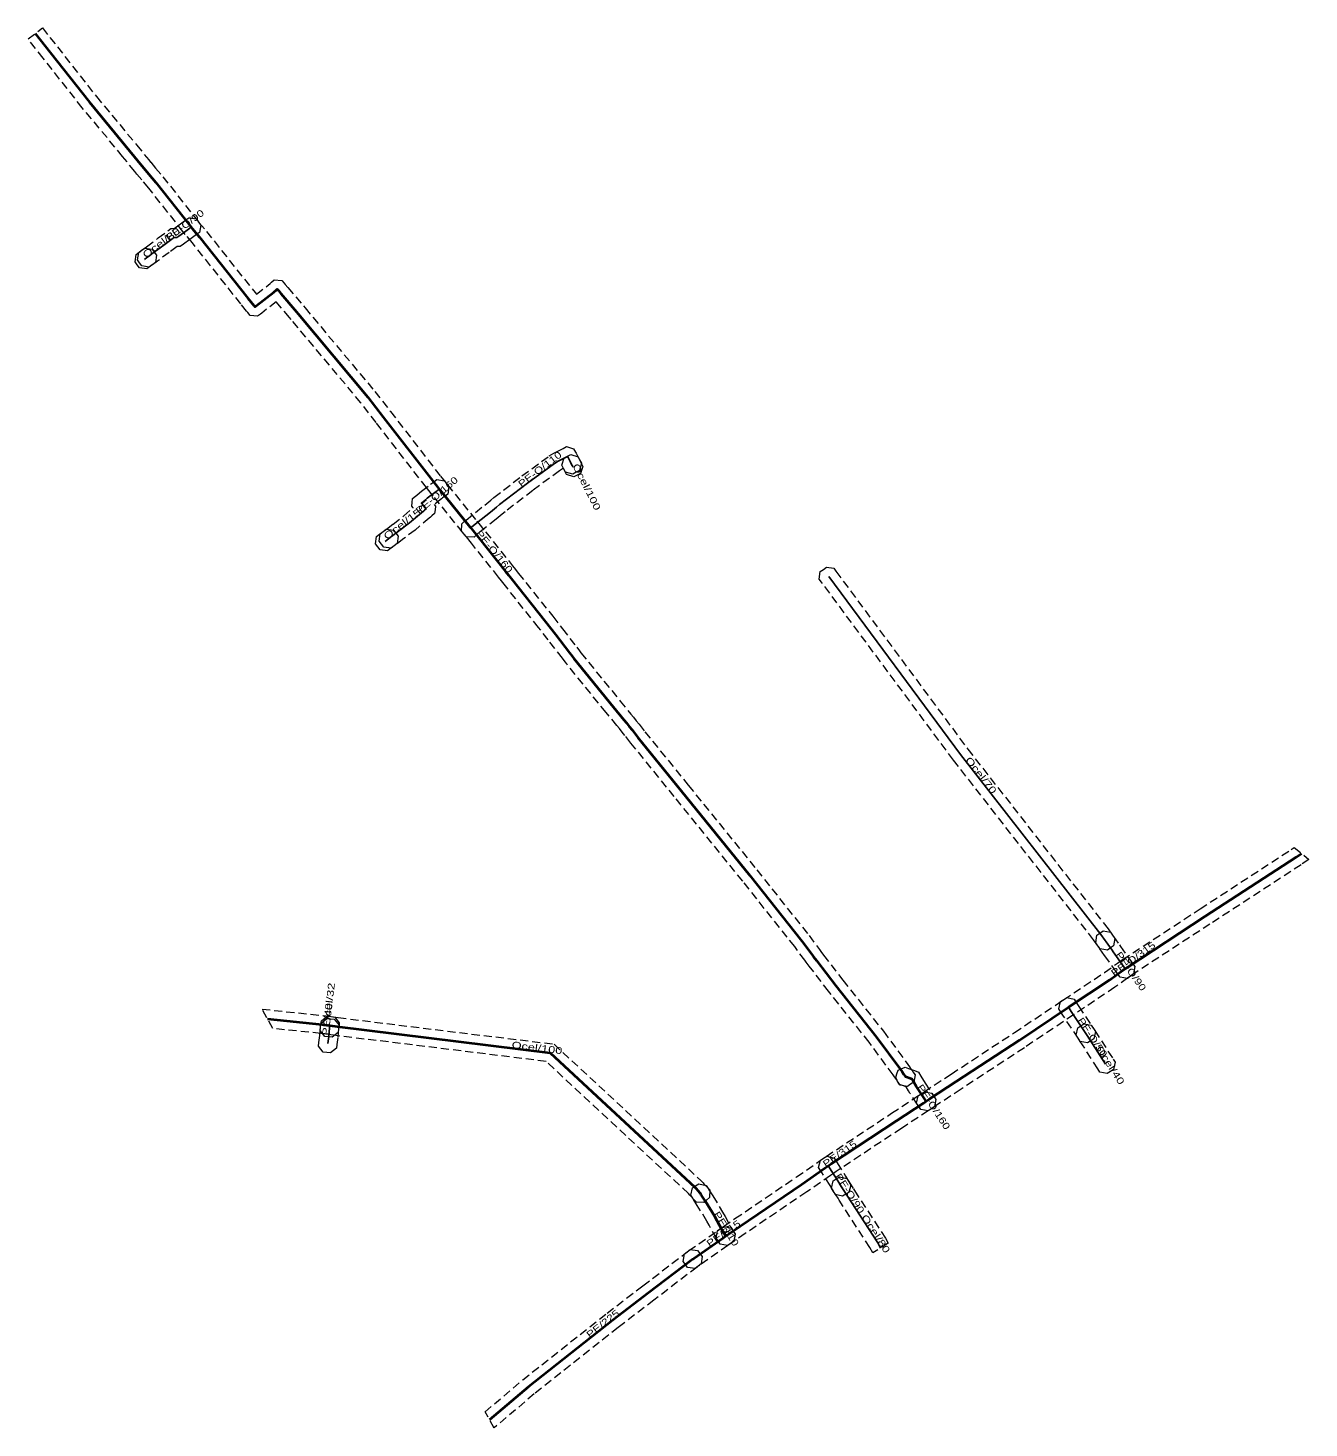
# Model space of a CAD drawing. Extents: x -570499 to -570358, y -1086802 to -1086647.
import ezdxf

# ---------------------------------------------------------------- set-up
doc = ezdxf.new("R2010")
doc.units = 0
doc.header["$LTSCALE"] = 0.3
doc.linetypes.add('MEDIUM_DASHED', pattern=[4.5, 3, -1.5])
doc.layers.add('1', color=7, linetype='MEDIUM_DASHED', lineweight=13)
doc.layers.add('14', color=7, linetype='Continuous', lineweight=25)
doc.layers.add('20', color=7, linetype='Continuous')

msp = doc.modelspace()

# ---------------------------------------------------------------- linework, layer by layer
at = {"layer": '1'}
for points in [[(-570499.087, -1086648.44), (-570497.496, -1086647.229), (-570495.845, -1086649.321), (-570491.532, -1086654.791), (-570487.086, -1086660.157), (-570485.75, -1086661.812), (-570485.54, -1086662.059), (-570485.531, -1086662.069), (-570484.995, -1086662.706), (-570484.194, -1086663.659), (-570480.397, -1086668.478), (-570480.29, -1086668.612), (-570480.176, -1086668.745), (-570479.374, -1086669.709), (-570473.998, -1086676.477), (-570473.855, -1086676.656), (-570472.556, -1086675.648), (-570472.335, -1086675.454), (-570472.191, -1086675.331), (-570471.877, -1086675.061), (-570471.051, -1086675.125), (-570470.781, -1086675.439), (-570470.659, -1086675.581), (-570470.377, -1086675.913), (-570468.661, -1086677.94), (-570468.48, -1086678.162), (-570460.761, -1086687.383), (-570459.039, -1086689.608), (-570453.507, -1086696.768), (-570452.993, -1086697.399), (-570452.867, -1086697.545), (-570452.748, -1086697.697), (-570449.498, -1086701.717), (-570449.397, -1086701.845), (-570449.283, -1086701.979), (-570448.521, -1086702.913), (-570445.549, -1086706.656), (-570445.214, -1086707.072), (-570444.913, -1086707.463), (-570441.104, -1086712.242), (-570440.029, -1086713.629), (-570438.456, -1086715.672), (-570438.169, -1086716.048), (-570437.998, -1086716.267), (-570433.668, -1086721.605), (-570432.465, -1086723.047), (-570432.177, -1086723.408), (-570431.876, -1086723.789), (-570431.567, -1086724.178), (-570430.919, -1086724.995), (-570426.133, -1086730.911), (-570418.56, -1086740.254), (-570412.787, -1086747.531), (-570411.644, -1086749.068), (-570411.491, -1086749.278), (-570411.179, -1086749.678), (-570409.052, -1086752.455), (-570404.566, -1086758.102), (-570401.864, -1086761.762), (-570401.685, -1086762.025), (-570401.487, -1086762.312), (-570401.398, -1086762.441), (-570401.308, -1086762.571), (-570401.072, -1086762.911), (-570401.221, -1086763.726), (-570401.561, -1086763.962), (-570401.901, -1086764.198), (-570402.716, -1086764.049), (-570402.952, -1086763.709), (-570403.042, -1086763.579), (-570403.133, -1086763.448), (-570403.335, -1086763.155), (-570403.496, -1086762.918), (-570406.154, -1086759.318), (-570410.628, -1086753.685), (-570412.761, -1086750.902), (-570413.089, -1086750.482), (-570413.256, -1086750.252), (-570414.373, -1086748.749), (-570420.12, -1086741.506), (-570427.687, -1086732.169), (-570432.481, -1086726.245), (-570433.133, -1086725.422), (-570433.444, -1086725.031), (-570433.743, -1086724.652), (-570434.015, -1086724.313), (-570435.212, -1086722.875), (-570439.562, -1086717.513), (-570439.751, -1086717.272), (-570440.044, -1086716.888), (-570441.611, -1086714.851), (-570442.676, -1086713.478), (-570446.487, -1086708.697), (-570446.786, -1086708.308), (-570447.111, -1086707.904), (-570450.079, -1086704.167), (-570450.817, -1086703.261), (-570450.943, -1086703.115), (-570451.062, -1086702.963), (-570454.312, -1086698.943), (-570454.413, -1086698.815)], [(-570454.413, -1086698.815), (-570454.527, -1086698.681), (-570455.073, -1086698.012), (-570460.621, -1086690.832), (-570462.319, -1086688.637), (-570470.02, -1086679.438), (-570470.199, -1086679.22), (-570471.665, -1086677.488), (-570473.265, -1086678.728), (-570473.402, -1086678.836), (-570473.724, -1086679.089), (-570474.538, -1086678.999), (-570474.796, -1086678.681), (-570474.929, -1086678.517), (-570475.562, -1086677.723), (-570480.926, -1086670.971), (-570481.704, -1086670.035), (-570481.83, -1086669.888), (-570481.963, -1086669.722), (-570485.746, -1086664.921), (-570486.525, -1086663.994), (-570487.049, -1086663.371), (-570487.054, -1086663.365), (-570487.29, -1086663.088), (-570488.634, -1086661.423), (-570493.088, -1086656.049), (-570497.415, -1086650.559), (-570499.087, -1086648.44)]]:
    msp.add_lwpolyline(points, dxfattribs=at)
for points in [[(-570483.303, -1086669.39), (-570482.946, -1086669.39), (-570482.402, -1086668.984), (-570481.783, -1086668.538), (-570481.641, -1086668.436), (-570481.304, -1086668.195), (-570480.487, -1086668.332), (-570480.246, -1086668.669), (-570480.005, -1086669.006), (-570480.142, -1086669.823), (-570480.479, -1086670.064), (-570480.617, -1086670.162), (-570481.218, -1086670.596), (-570481.921, -1086671.121), (-570482.267, -1086671.38), (-570482.623, -1086671.38), (-570483.491, -1086672.031), (-570484.791, -1086673.001), (-570485.082, -1086673.219), (-570485.365, -1086673.418), (-570485.703, -1086673.656), (-570486.519, -1086673.514), (-570486.758, -1086673.175), (-570486.996, -1086672.837), (-570486.854, -1086672.021), (-570486.515, -1086671.782), (-570486.258, -1086671.601), (-570485.989, -1086671.399), (-570484.689, -1086670.429), (-570483.65, -1086669.65)], [(-570485.012, -1086673.157), (-570485.345, -1086673.404), (-570485.615, -1086673.604), (-570485.948, -1086673.85), (-570486.767, -1086673.728), (-570487.014, -1086673.395), (-570487.26, -1086673.062), (-570487.138, -1086672.243), (-570486.805, -1086671.996), (-570486.535, -1086671.796), (-570486.202, -1086671.55), (-570485.383, -1086671.672), (-570485.136, -1086672.005), (-570484.89, -1086672.338)], [(-570439.891, -1086695.942), (-570439.909, -1086695.911), (-570440.013, -1086695.964), (-570440.375, -1086696.183), (-570443.309, -1086698.329), (-570446.358, -1086700.683), (-570446.68, -1086700.947), (-570447.14, -1086701.317), (-570447.361, -1086701.497), (-570449.388, -1086703.119), (-570449.492, -1086703.215), (-570449.796, -1086703.496), (-570450.624, -1086703.462), (-570450.905, -1086703.158), (-570451.186, -1086702.854), (-570451.152, -1086702.026), (-570450.848, -1086701.745), (-570450.692, -1086701.601), (-570448.619, -1086699.943), (-570448.4, -1086699.763), (-570447.94, -1086699.393), (-570447.602, -1086699.117), (-570444.511, -1086696.731), (-570441.485, -1086694.517), (-570440.987, -1086694.216), (-570440.168, -1086693.797), (-570440.087, -1086693.755), (-570439.964, -1086693.69), (-570439.599, -1086693.493), (-570438.806, -1086693.731), (-570438.61, -1086694.096), (-570438.536, -1086694.233), (-570438.271, -1086694.743), (-570438.149, -1086694.958), (-570437.945, -1086695.319), (-570438.167, -1086696.117), (-570438.528, -1086696.321), (-570438.889, -1086696.525), (-570439.687, -1086696.303)], [(-570438.311, -1086694.632), (-570438.126, -1086695.003), (-570438.007, -1086695.241), (-570437.976, -1086695.303), (-570437.79, -1086695.673), (-570438.052, -1086696.459), (-570438.423, -1086696.644), (-570438.793, -1086696.83), (-570439.579, -1086696.568), (-570439.764, -1086696.197), (-570439.795, -1086696.135), (-570439.914, -1086695.897), (-570440.1, -1086695.527), (-570439.838, -1086694.741), (-570439.467, -1086694.556), (-570439.097, -1086694.37)], [(-570457.567, -1086701.151), (-570456.515, -1086700.256), (-570456.663, -1086700.085), (-570456.626, -1086699.663), (-570456.589, -1086699.241), (-570456.261, -1086698.974), (-570456.112, -1086698.853), (-570455.821, -1086698.602), (-570455.591, -1086698.416), (-570454.606, -1086697.654), (-570454.487, -1086697.565), (-570454.393, -1086697.492), (-570454.231, -1086697.374), (-570453.897, -1086697.129), (-570453.079, -1086697.255), (-570452.834, -1086697.589), (-570452.589, -1086697.923), (-570452.715, -1086698.741), (-570453.049, -1086698.986), (-570453.187, -1086699.088), (-570453.273, -1086699.155), (-570453.394, -1086699.246), (-570454.221, -1086699.885), (-570454.074, -1086700.061), (-570454.115, -1086700.477), (-570454.155, -1086700.893), (-570454.479, -1086701.156), (-570454.632, -1086701.28), (-570454.753, -1086701.383), (-570456.313, -1086702.709), (-570457.547, -1086703.647), (-570458.35, -1086704.252), (-570458.455, -1086704.319), (-570458.639, -1086704.461), (-570458.967, -1086704.714), (-570459.788, -1086704.609), (-570460.041, -1086704.281), (-570460.294, -1086703.953), (-570460.189, -1086703.132), (-570459.861, -1086702.879), (-570459.605, -1086702.681), (-570459.49, -1086702.608), (-570458.753, -1086702.053)], [(-570458.314, -1086704.214), (-570458.643, -1086704.465), (-570459.023, -1086704.755), (-570459.352, -1086705.006), (-570460.174, -1086704.896), (-570460.425, -1086704.567), (-570460.676, -1086704.238), (-570460.566, -1086703.416), (-570460.237, -1086703.165), (-570459.857, -1086702.875), (-570459.528, -1086702.624), (-570458.706, -1086702.734), (-570458.455, -1086703.063), (-570458.204, -1086703.392)], [(-570410.057, -1086706.934), (-570409.811, -1086707.267), (-570395.253, -1086726.915), (-570379.735, -1086746.796), (-570379.243, -1086747.494), (-570379.004, -1086747.832), (-570379.145, -1086748.648), (-570379.484, -1086748.887), (-570379.822, -1086749.126), (-570380.638, -1086748.985), (-570380.877, -1086748.646), (-570381.341, -1086747.988), (-570396.845, -1086728.125), (-570411.417, -1086708.457), (-570411.664, -1086708.124), (-570411.542, -1086707.305), (-570411.209, -1086707.059), (-570410.876, -1086706.812)], [(-570359.521, -1086738.026), (-570359.179, -1086737.797), (-570357.548, -1086739.11), (-570358.419, -1086739.694), (-570368.494, -1086746.258), (-570377.016, -1086751.826), (-570377.279, -1086752.014), (-570377.559, -1086752.214), (-570379.002, -1086753.243), (-570383.555, -1086756.282), (-570388.998, -1086759.914), (-570395.992, -1086764.506), (-570398.963, -1086766.451), (-570399.273, -1086766.664), (-570399.615, -1086766.899), (-570400.43, -1086766.748), (-570400.664, -1086766.407), (-570400.899, -1086766.065), (-570400.748, -1086765.25), (-570400.407, -1086765.016), (-570400.077, -1086764.789), (-570397.088, -1086762.834), (-570390.102, -1086758.246), (-570384.665, -1086754.618), (-570380.138, -1086751.597), (-570378.721, -1086750.586), (-570378.441, -1086750.386), (-570378.144, -1086750.174), (-570369.586, -1086744.582)], [(-570378.425, -1086752.123), (-570378.669, -1086751.788), (-570378.834, -1086751.561), (-570379.999, -1086749.899), (-570380.129, -1086749.714), (-570380.777, -1086748.787), (-570380.874, -1086748.651), (-570381.115, -1086748.314), (-570380.978, -1086747.497), (-570380.641, -1086747.256), (-570380.304, -1086747.015), (-570379.487, -1086747.152), (-570379.246, -1086747.489), (-570379.143, -1086747.633), (-570378.491, -1086748.566), (-570378.361, -1086748.751), (-570377.206, -1086750.399), (-570377.051, -1086750.612), (-570376.807, -1086750.947), (-570376.937, -1086751.765), (-570377.272, -1086752.009), (-570377.607, -1086752.253)], [(-570383.488, -1086754.563), (-570383.266, -1086754.913), (-570383.198, -1086755.02), (-570382.983, -1086755.352), (-570381.376, -1086757.778), (-570381.147, -1086758.123), (-570381.313, -1086758.935), (-570381.658, -1086759.164), (-570382.003, -1086759.393), (-570382.815, -1086759.227), (-570383.044, -1086758.882), (-570384.657, -1086756.448), (-570384.882, -1086756.1), (-570384.954, -1086755.987), (-570385.176, -1086755.637), (-570384.997, -1086754.828), (-570384.647, -1086754.606), (-570384.297, -1086754.384)], [(-570466.72, -1086758.343), (-570472.049, -1086757.791), (-570473.23, -1086755.658), (-570466.48, -1086756.357), (-570465.593, -1086756.479), (-570464.81, -1086756.588), (-570440.966, -1086759.526), (-570424.697, -1086774.628), (-570424.487, -1086774.861), (-570424.401, -1086774.956), (-570424.048, -1086775.338), (-570423.767, -1086775.642), (-570423.799, -1086776.47), (-570424.103, -1086776.751), (-570424.407, -1086777.032), (-570425.235, -1086777), (-570425.516, -1086776.696), (-570425.879, -1086776.304), (-570425.973, -1086776.199), (-570426.123, -1086776.032), (-570441.852, -1086761.432), (-570465.07, -1086758.572), (-570465.867, -1086758.461)], [(-570464.722, -1086757.413), (-570464.765, -1086757.825), (-570464.866, -1086758.78), (-570464.957, -1086759.565), (-570465.004, -1086759.976), (-570465.653, -1086760.491), (-570466.065, -1086760.443), (-570466.476, -1086760.396), (-570466.991, -1086759.747), (-570466.943, -1086759.335), (-570466.854, -1086758.56), (-570466.755, -1086757.615), (-570466.712, -1086757.203), (-570466.067, -1086756.682), (-570465.655, -1086756.725), (-570465.243, -1086756.768)], [(-570464.688, -1086757.178), (-570464.737, -1086757.589), (-570464.767, -1086757.839), (-570464.816, -1086758.25), (-570465.468, -1086758.762), (-570465.879, -1086758.713), (-570466.29, -1086758.664), (-570466.802, -1086758.012), (-570466.753, -1086757.601), (-570466.723, -1086757.351), (-570466.674, -1086756.94), (-570466.022, -1086756.428), (-570465.611, -1086756.477), (-570465.2, -1086756.526)], [(-570380.651, -1086762.608), (-570380.875, -1086762.259), (-570382.9, -1086759.103), (-570383.048, -1086758.876), (-570383.274, -1086758.529), (-570383.103, -1086757.719), (-570382.756, -1086757.492), (-570382.409, -1086757.266), (-570381.599, -1086757.437), (-570381.372, -1086757.784), (-570381.22, -1086758.017), (-570379.191, -1086761.179), (-570378.967, -1086761.528), (-570379.144, -1086762.337), (-570379.493, -1086762.561), (-570379.842, -1086762.785)], [(-570401.797, -1086764.696), (-570402.059, -1086764.226), (-570402.464, -1086764.082), (-570402.855, -1086763.944), (-570403.211, -1086763.196), (-570403.072, -1086762.806), (-570402.934, -1086762.415), (-570402.186, -1086762.059), (-570401.796, -1086762.198), (-570401.145, -1086762.428), (-570400.685, -1086762.626), (-570400.426, -1086763.046), (-570400.319, -1086763.239), (-570400.083, -1086763.664), (-570399.974, -1086763.831), (-570399.167, -1086765.046), (-570399.008, -1086765.285), (-570398.778, -1086765.63), (-570398.94, -1086766.442), (-570399.285, -1086766.672), (-570399.63, -1086766.902), (-570400.442, -1086766.74), (-570400.672, -1086766.395), (-570400.833, -1086766.154), (-570401.646, -1086764.929)], [(-570422.918, -1086780.14), (-570422.577, -1086779.906), (-570422.257, -1086779.686), (-570420.973, -1086778.804), (-570414.175, -1086774.205), (-570411.561, -1086772.389), (-570411.229, -1086772.158), (-570410.899, -1086771.93), (-570403.67, -1086767.165), (-570400.709, -1086765.214), (-570400.389, -1086765.004), (-570400.043, -1086764.777), (-570399.231, -1086764.945), (-570399.004, -1086765.291), (-570398.777, -1086765.637), (-570398.945, -1086766.449), (-570399.291, -1086766.676), (-570399.611, -1086766.886), (-570402.57, -1086768.835), (-570409.781, -1086773.59), (-570410.091, -1086773.802), (-570410.419, -1086774.031), (-570413.045, -1086775.855), (-570419.847, -1086780.456), (-570421.123, -1086781.334), (-570421.443, -1086781.554), (-570421.785, -1086781.789), (-570422.6, -1086781.638), (-570422.834, -1086781.297), (-570423.069, -1086780.955)], [(-570410.016, -1086772.111), (-570409.803, -1086772.466), (-570409.69, -1086772.653), (-570408.758, -1086774.107), (-570408.378, -1086774.754), (-570408.168, -1086775.111), (-570408.377, -1086775.912), (-570408.734, -1086776.122), (-570409.091, -1086776.332), (-570409.892, -1086776.123), (-570410.102, -1086775.766), (-570410.462, -1086775.153), (-570411.39, -1086773.707), (-570411.517, -1086773.494), (-570411.73, -1086773.139), (-570411.529, -1086772.336), (-570411.174, -1086772.123), (-570410.819, -1086771.91)], [(-570404.032, -1086781.53), (-570405.727, -1086782.598), (-570406.059, -1086781.999), (-570409.468, -1086776.76), (-570409.588, -1086776.56), (-570410.079, -1086775.805), (-570410.304, -1086775.457), (-570410.132, -1086774.647), (-570409.785, -1086774.421), (-570409.437, -1086774.196), (-570408.627, -1086774.368), (-570408.401, -1086774.715), (-570407.892, -1086775.5), (-570407.772, -1086775.7), (-570404.345, -1086780.967)], [(-570422.621, -1086781.623), (-570422.848, -1086781.276), (-570423.02, -1086781.012), (-570423.829, -1086779.517), (-570424.065, -1086779.082), (-570425.132, -1086777.354), (-570425.537, -1086776.692), (-570425.623, -1086776.558), (-570425.847, -1086776.21), (-570425.671, -1086775.4), (-570425.323, -1086775.176), (-570424.975, -1086774.952), (-570424.165, -1086775.128), (-570423.941, -1086775.476), (-570423.843, -1086775.628), (-570423.428, -1086776.306), (-570422.335, -1086778.078), (-570422.071, -1086778.563), (-570421.3, -1086779.988), (-570421.172, -1086780.184), (-570420.946, -1086780.531), (-570421.117, -1086781.341), (-570421.464, -1086781.568), (-570421.811, -1086781.794)], [(-570426.565, -1086782.709), (-570426.231, -1086782.464), (-570426.072, -1086782.347), (-570422.895, -1086780.132), (-570422.589, -1086779.914), (-570422.251, -1086779.675), (-570421.434, -1086779.813), (-570421.194, -1086780.151), (-570420.955, -1086780.489), (-570421.093, -1086781.306), (-570421.431, -1086781.546), (-570421.745, -1086781.768), (-570424.908, -1086783.973), (-570425.049, -1086784.076), (-570425.383, -1086784.321), (-570426.201, -1086784.195), (-570426.446, -1086783.861), (-570426.691, -1086783.527)], [(-570447.592, -1086801.945), (-570448.581, -1086800.161), (-570444.424, -1086796.627), (-570435.094, -1086789.251), (-570431.148, -1086786.226), (-570426.393, -1086782.59), (-570426.258, -1086782.484), (-570425.932, -1086782.228), (-570425.11, -1086782.326), (-570424.854, -1086782.652), (-570424.598, -1086782.978), (-570424.696, -1086783.8), (-570425.022, -1086784.056), (-570425.167, -1086784.17), (-570429.932, -1086787.814), (-570433.866, -1086790.829), (-570443.156, -1086798.173)]]:
    msp.add_lwpolyline(points, close=True, dxfattribs=at)
at = {"layer": '14'}
for p, q in [((-570459.25, -1086703.67), (-570459.63, -1086703.96)), ((-570465.73, -1086757.47), (-570465.76, -1086757.72))]:
    msp.add_line(p, q, dxfattribs=at)
at = {"layer": '14', "lineweight": 40}
for points in [[(-570498.291, -1086647.834), (-570496.63, -1086649.94), (-570492.31, -1086655.42), (-570487.86, -1086660.79), (-570486.52, -1086662.45), (-570486.297, -1086662.712), (-570486.29, -1086662.72), (-570485.76, -1086663.35), (-570484.97, -1086664.29), (-570481.18, -1086669.1), (-570481.06, -1086669.25), (-570480.94, -1086669.39), (-570480.15, -1086670.34), (-570474.78, -1086677.1), (-570474.15, -1086677.89), (-570474.02, -1086678.05), (-570473.88, -1086677.94), (-570471.92, -1086676.42), (-570471.68, -1086676.21), (-570471.54, -1086676.09), (-570471.42, -1086676.23), (-570471.14, -1086676.56), (-570469.43, -1086678.58), (-570469.25, -1086678.8), (-570461.54, -1086688.01), (-570459.83, -1086690.22), (-570454.29, -1086697.39), (-570453.76, -1086698.04), (-570453.64, -1086698.18), (-570453.53, -1086698.32), (-570450.28, -1086702.34), (-570450.17, -1086702.48), (-570450.05, -1086702.62), (-570449.3, -1086703.54), (-570446.33, -1086707.28), (-570446, -1086707.69), (-570445.7, -1086708.08), (-570441.89, -1086712.86), (-570440.82, -1086714.24), (-570439.25, -1086716.28), (-570438.96, -1086716.66), (-570438.78, -1086716.89), (-570434.44, -1086722.24), (-570433.24, -1086723.68), (-570432.96, -1086724.03), (-570432.66, -1086724.41), (-570432.35, -1086724.8), (-570431.7, -1086725.62), (-570426.91, -1086731.54), (-570419.34, -1086740.88), (-570413.58, -1086748.14), (-570412.45, -1086749.66), (-570412.29, -1086749.88), (-570411.97, -1086750.29), (-570409.84, -1086753.07), (-570405.36, -1086758.71), (-570402.68, -1086762.34), (-570402.51, -1086762.59), (-570402.31, -1086762.88), (-570402.22, -1086763.01), (-570402.13, -1086763.14)], [(-570399.84, -1086765.84), (-570399.52, -1086765.62), (-570396.54, -1086763.67), (-570389.55, -1086759.08), (-570384.11, -1086755.45), (-570379.57, -1086752.42), (-570378.14, -1086751.4), (-570377.86, -1086751.2), (-570377.58, -1086751), (-570369.04, -1086745.42), (-570358.97, -1086738.86), (-570358.364, -1086738.453)], [(-570472.64, -1086756.724), (-570466.6, -1086757.35), (-570465.73, -1086757.47), (-570464.94, -1086757.58), (-570441.409, -1086760.479), (-570425.41, -1086775.33), (-570425.23, -1086775.53), (-570425.14, -1086775.63), (-570424.782, -1086776.017)], [(-570399.84, -1086765.84), (-570400, -1086765.6), (-570400.81, -1086764.38), (-570400.94, -1086764.18), (-570401.194, -1086763.724), (-570401.29, -1086763.55), (-570401.37, -1086763.42), (-570401.51, -1086763.36), (-570402.13, -1086763.14)], [(-570422.01, -1086780.73), (-570421.69, -1086780.51), (-570420.41, -1086779.63), (-570413.61, -1086775.03), (-570410.99, -1086773.21), (-570410.66, -1086772.98), (-570410.34, -1086772.76), (-570403.12, -1086768), (-570400.16, -1086766.05), (-570399.84, -1086765.84)], [(-570422.01, -1086780.73), (-570422.16, -1086780.5), (-570422.95, -1086779.04), (-570423.2, -1086778.58), (-570424.28, -1086776.83), (-570424.69, -1086776.16), (-570424.782, -1086776.017)], [(-570425.64, -1086783.27), (-570425.49, -1086783.16), (-570422.32, -1086780.95), (-570422.01, -1086780.73)], [(-570425.64, -1086783.27), (-570425.78, -1086783.38), (-570430.54, -1086787.02), (-570434.48, -1086790.04), (-570443.79, -1086797.4), (-570448.087, -1086801.053)]]:
    msp.add_lwpolyline(points, dxfattribs=at)
at = {"layer": '14'}
for points in [[(-570481.06, -1086669.25), (-570481.2, -1086669.35), (-570481.81, -1086669.79), (-570482.52, -1086670.32), (-570482.6, -1086670.38), (-570482.7, -1086670.38), (-570482.87, -1086670.39), (-570482.97, -1086670.39), (-570483.05, -1086670.45), (-570484.09, -1086671.23), (-570485.39, -1086672.2), (-570485.67, -1086672.41), (-570485.94, -1086672.6), (-570486.21, -1086672.8)], [(-570450.17, -1086702.48), (-570450.04, -1086702.36), (-570447.99, -1086700.72), (-570447.77, -1086700.54), (-570447.31, -1086700.17), (-570446.98, -1086699.9), (-570443.91, -1086697.53), (-570440.93, -1086695.35), (-570440.5, -1086695.09), (-570439.711, -1086694.687), (-570439.62, -1086694.64), (-570439.49, -1086694.57), (-570439.42, -1086694.7), (-570439.15, -1086695.22), (-570439.02, -1086695.45)], [(-570439.02, -1086695.45), (-570438.901, -1086695.688), (-570438.87, -1086695.75)], [(-570453.64, -1086698.18), (-570453.79, -1086698.29), (-570453.88, -1086698.36), (-570454, -1086698.45), (-570454.97, -1086699.2), (-570455.18, -1086699.37), (-570455.47, -1086699.62), (-570455.63, -1086699.75), (-570455.5, -1086699.9), (-570455.26, -1086700.2), (-570455.11, -1086700.38), (-570455.27, -1086700.51), (-570455.4, -1086700.62), (-570456.94, -1086701.93), (-570458.15, -1086702.85), (-570458.92, -1086703.43), (-570459.03, -1086703.5), (-570459.25, -1086703.67)], [(-570410.614, -1086707.862), (-570396.049, -1086727.52), (-570380.538, -1086747.392), (-570380.06, -1086748.07)], [(-570377.86, -1086751.2), (-570378.02, -1086750.98), (-570379.18, -1086749.325), (-570379.31, -1086749.14), (-570379.96, -1086748.21), (-570380.06, -1086748.07)], [(-570384.11, -1086755.45), (-570384.04, -1086755.56), (-570383.82, -1086755.9), (-570382.21, -1086758.33)], [(-570465.76, -1086757.72), (-570465.86, -1086758.67), (-570465.95, -1086759.45)], [(-570380.033, -1086761.719), (-570382.06, -1086758.56), (-570382.21, -1086758.33)], [(-570410.66, -1086772.98), (-570410.54, -1086773.18), (-570409.61, -1086774.63), (-570409.24, -1086775.26)], [(-570409.24, -1086775.26), (-570408.74, -1086776.03), (-570408.62, -1086776.23), (-570405.202, -1086781.483), (-570404.88, -1086782.064)]]:
    msp.add_lwpolyline(points, dxfattribs=at)

# ---------------------------------------------------------------- texts
at = {"layer": '20'}
for s, rotation, width, p in [('PE-O/90', 36.87, 1.3, (-570483.539, -1086670.816)), ('Ocel/80', 36.529, 1.4, (-570486.075, -1086672.7)), ('PE-O/110', 37.668, 1.3, (-570444.564, -1086698.035)), ('Ocel/100', 296.565, 1.4, (-570438.945, -1086695.6)), ('PE-O/160', 40.386, 1.3, (-570455.852, -1086701.004)), ('Ocel/150', 37.349, 1.4, (-570459.44, -1086703.815)), ('PE-O/160', 309.188, 1.3, (-570449.66, -1086703.099)), ('Ocel/70', 307.974, 1.4, (-570395.565, -1086728.14)), ('PE-O/315', 35.5, 1.3, (-570379.088, -1086752.076)), ('PE-O/90', 305.027, 1.3, (-570378.962, -1086749.636)), ('Ocel/32', 83.157, 1.4, (-570465.745, -1086757.595)), ('PE/40', 83.991, 1.3, (-570465.851, -1086758.585)), ('PE-O/50', 303.527, 1.3, (-570383.163, -1086756.892)), ('Ocel/100', 352.977, 1.4, (-570445.675, -1086759.953)), ('Ocel/40', 302.687, 1.4, (-570381.12, -1086760.024)), ('PE-O/160', 303.024, 1.3, (-570400.883, -1086764.267)), ('PE/315', 34.875, 1.3, (-570410.939, -1086773.174)), ('PE-O/90', 302.675, 1.3, (-570409.941, -1086774.114)), ('PE/315', 34.883, 1.3, (-570423.785, -1086781.971)), ('PE/110', 301.681, 1.3, (-570423.371, -1086778.302)), ('Ocel/80', 303.051, 1.4, (-570407.044, -1086778.652)), ('PE/225', 38.328, 1.3, (-570437.019, -1086792.047))]:
    msp.add_text(s, height=0.75, rotation=rotation, dxfattribs=dict(at, width=width)).set_placement(p)

doc.saveas('drawing.dxf')
